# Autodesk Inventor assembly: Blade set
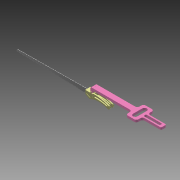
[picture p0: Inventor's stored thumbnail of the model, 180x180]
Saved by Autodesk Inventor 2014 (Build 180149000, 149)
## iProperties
Created: 2008-07
Part Number: Blade set
Document SubType Name: Assembly
Designer: tangg
Mass: 233.304 g
Surface Area: 206.898 cm^2
Volume: 29.7477 cm^3
Density: 7.84277 g/cm^3
Author: tangg
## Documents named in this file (4)
- C:\Users\iTools\Desktop\tutorial files\Dynamic Simulation 1 and 2\Blade set.iam
- C:\Users\iTools\Desktop\tutorial files\Dynamic Simulation 1 and 2\Blade clamp.ipt
- C:\Users\iTools\Desktop\tutorial files\Dynamic Simulation 1 and 2\Saw blade.ipt
- C:\Users\iTools\Desktop\tutorial files\Dynamic Simulation 1 and 2\Scottish Yoke.ipt
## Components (3 placed, 3 different names)
1. Scottish Yoke:1 — Mate:1, Flush:1
2. Blade clamp:1 — Mate:1, Flush:1, Mate:2, Mate:4
3. Saw blade:1 — Mate:2, Mate:4
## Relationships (4: Mate 3, Flush 1)
- Mate:1: Scottish Yoke:1 ↔ Blade clamp:1
- Flush:1: Scottish Yoke:1 ↔ Blade clamp:1
- Mate:2: Blade clamp:1 ↔ Saw blade:1
- Mate:4: Blade clamp:1 ↔ Saw blade:1
